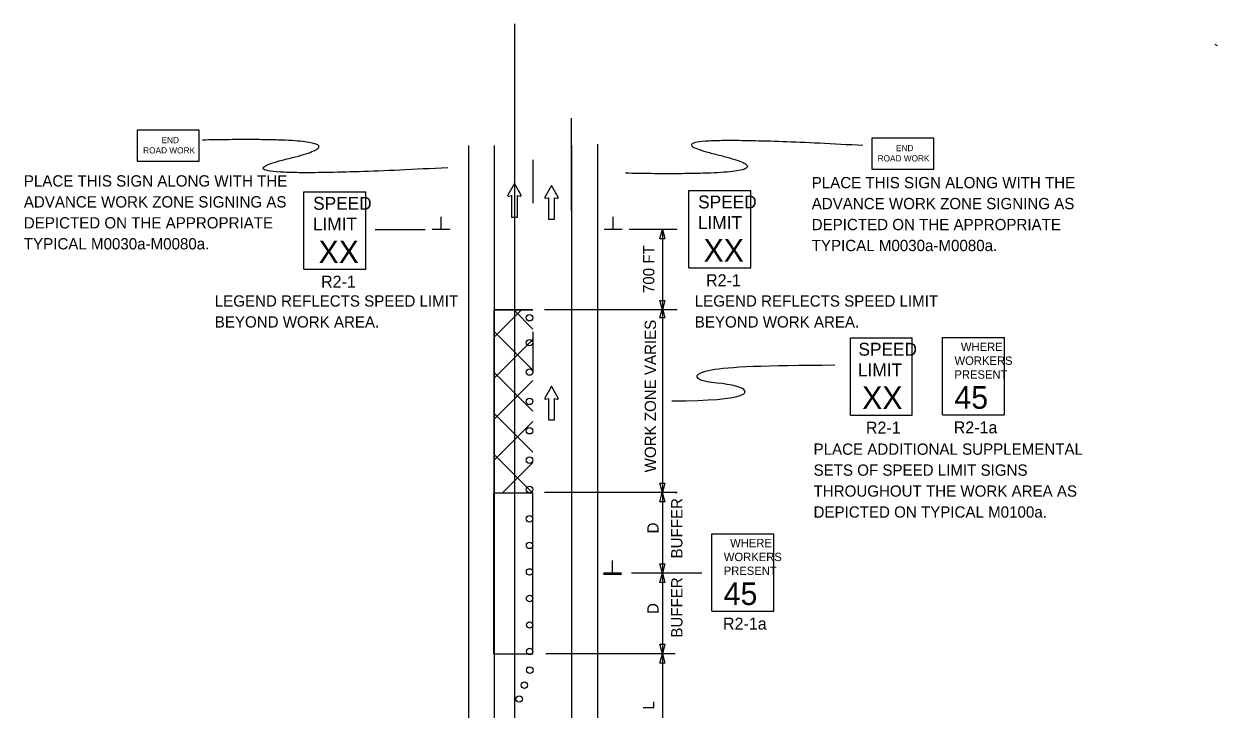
# Model space of a CAD drawing. Extents: x 15278 to 18126, y 1908 to 6555.
# Drawn here: x 15278 to 16017, y 2813 to 3238 of the extents above; entities that cross this region are included whole.
import ezdxf

# ---------------------------------------------------------------- set-up
doc = ezdxf.new("R2010")
doc.units = 0
for name, color, linetype in [('ALI_LEGAL_EX', 7, 'Continuous'), ('MT_SCRATCH_LEVEL_E', 7, 'Continuous'), ('PAVT_EDGE_EX', 7, 'Continuous'), ('TRAFFIC_SIGNS_PR', 7, 'Continuous'), ('TYPICAL_TEXT_DIMEN_PR', 7, 'Continuous')]:
    doc.layers.add(name, color=color, linetype=linetype)

msp = doc.modelspace()

# ---------------------------------------------------------------- linework, layer by layer
at = {"layer": 'ALI_LEGAL_EX'}
msp.add_line((15581.68, 3237.79), (15581.68, 2408.6), dxfattribs=at)
for points in [[(15593.04, 3153.46), (15593.04, 3126.45)], [(15593.04, 3046.7), (15593.04, 3021.3)], [(15593.04, 3021.3), (15593.04, 3021.3)], [(15590.55, 3007.79), (15590.55, 3007.79)]]:
    msp.add_lwpolyline(points, dxfattribs=at)
at = {"layer": 'MT_SCRATCH_LEVEL_E'}
for p, q in [((15581.51, 3138.81), (15577.39, 3131.57)), ((15585.65, 3131.57), (15581.51, 3138.81)), ((15604.48, 3137.54), (15600.37, 3130.3)), ((15608.63, 3130.3), (15604.48, 3137.54)), ((15577.88, 3130.88), (15579.65, 3131.2)), ((15579.65, 3131.2), (15579.65, 3117.94)), ((15583.4, 3117.94), (15583.4, 3131.2)), ((15583.4, 3131.2), (15585.17, 3130.88)), ((15600.85, 3129.61), (15602.63, 3129.93)), ((15602.63, 3129.93), (15602.63, 3116.67)), ((15606.37, 3116.67), (15606.37, 3129.93)), ((15606.37, 3129.93), (15608.15, 3129.61)), ((15579.65, 3117.94), (15583.4, 3117.94)), ((15602.63, 3116.67), (15606.37, 3116.67)), ((15604.48, 3012.92), (15600.37, 3005.68)), ((15608.63, 3005.68), (15604.48, 3012.92)), ((15600.85, 3005), (15602.63, 3005.31)), ((15602.63, 3005.31), (15602.63, 2992.06)), ((15606.37, 2992.06), (15606.37, 3005.31)), ((15606.37, 3005.31), (15608.15, 3005)), ((15602.63, 2992.06), (15606.37, 2992.06))]:
    msp.add_line(p, q, dxfattribs=at)
for centre, start, end in [((15577.8, 3131.34), 150.42484, 279.96381), ((15585.24, 3131.34), 260.03619, 29.77312), ((15600.78, 3130.07), 150.42484, 279.96381), ((15608.22, 3130.07), 260.03619, 29.77312), ((15600.78, 3005.46), 150.42484, 279.96381), ((15608.22, 3005.46), 260.03619, 29.77312)]:
    msp.add_arc(centre, 0.463, start, end, dxfattribs=at)
at = {"layer": 'PAVT_EDGE_EX'}
for p, q in [((15617, 3154.14), (15617, 3179.34)), ((15553, 3162.29), (15553, 2476.81)), ((15569, 3162.29), (15569, 2476.81)), ((15617, 3162.29), (15617, 2476.81)), ((15633, 3163.21), (15633, 2476.81)), ((15617, 3122.08), (15617, 3154.14)), ((15569.04, 2946.61), (15569.04, 3060.33)), ((15569.04, 3060.33), (15593.04, 3060.33)), ((15593.04, 3060.33), (15569.04, 3060.33)), ((15569.04, 3043.52), (15585.85, 3060.33)), ((15593.04, 3048.43), (15581.14, 3060.33)), ((15593.04, 3022.98), (15569.04, 3046.98)), ((15569.04, 3018.07), (15593.04, 3042.07)), ((15593.04, 2997.52), (15569.04, 3021.52)), ((15569.04, 2992.61), (15593.04, 3016.61)), ((15593.04, 2972.07), (15569.04, 2996.07)), ((15569.04, 2967.16), (15593.04, 2991.16)), ((15593.04, 2946.61), (15569.04, 2970.61)), ((15573.95, 2946.61), (15593.04, 2965.7)), ((15592.91, 2946.61), (15569.04, 2946.61)), ((15589.94, 2838.71), (15589.89, 2838.83)), ((15568.93, 2815.26), (15568.88, 2815.38))]:
    msp.add_line(p, q, dxfattribs=at)
msp.add_lwpolyline([(15592.91, 2946.61), (15568.53, 2946.61), (15568.53, 2847.05), (15592.91, 2847.05)], close=True, dxfattribs=at)
at = {"layer": 'TRAFFIC_SIGNS_PR'}
for p, q in [((15451.02, 3133.58), (15489.43, 3133.58)), ((15451.02, 3085.58), (15451.02, 3133.58)), ((15489.43, 3085.58), (15489.43, 3133.58)), ((15689.66, 3134.43), (15728.06, 3134.43)), ((15689.66, 3086.43), (15689.66, 3134.43)), ((15728.06, 3086.43), (15728.06, 3134.43)), ((15451.02, 3085.58), (15489.43, 3085.58)), ((15689.66, 3086.43), (15728.06, 3086.43)), ((15789.78, 3043.07), (15828.18, 3043.07)), ((15789.78, 2995.07), (15789.78, 3043.07)), ((15828.18, 2995.07), (15828.18, 3043.07)), ((15846.98, 3043.15), (15885.38, 3043.15)), ((15846.98, 2995.15), (15846.98, 3043.15)), ((15885.38, 2995.15), (15885.38, 3043.15)), ((15789.78, 2995.07), (15828.18, 2995.07)), ((15846.98, 2995.15), (15885.38, 2995.15)), ((15703.97, 2921.41), (15742.37, 2921.41)), ((15703.97, 2873.41), (15703.97, 2921.41)), ((15742.37, 2873.41), (15742.37, 2921.41)), ((15703.97, 2873.41), (15742.37, 2873.41))]:
    msp.add_line(p, q, dxfattribs=at)
for points in [[(15347.83, 3152.63), (15386.23, 3152.63), (15386.23, 3171.83), (15347.83, 3171.83)], [(15803.06, 3147.67), (15841.46, 3147.67), (15841.46, 3166.87), (15803.06, 3166.87)]]:
    msp.add_lwpolyline(points, close=True, dxfattribs=at)
for centre in [(15590.9, 3055.46), (15590.94, 3040), (15590.94, 3021.78), (15590.94, 3003.57), (15590.94, 2985.36), (15590.94, 2967.14), (15590.94, 2948.93), (15590.94, 2930.71), (15590.96, 2914.25), (15590.97, 2897.79), (15590.99, 2881.32), (15591, 2864.86), (15591.02, 2848.39), (15591.08, 2836.84), (15587.71, 2827.56), (15584.49, 2818.97)]:
    msp.add_circle(centre, 2, dxfattribs=at)
for points in [[(15540.23, 3148.51), (15383.99, 3140.28), (15497.9, 3167.86), (15388.27, 3165.69)], [(15797.61, 3162.28), (15650.05, 3170.51), (15763.95, 3142.93), (15650.5, 3145.1)]]:
    msp.add_open_spline(points, degree=2, dxfattribs=at)
at = {"layer": 'TYPICAL_TEXT_DIMEN_PR'}
for p, q in [((16015.78, 3225.17), (16017.12, 3224.27)), ((15536.12, 3110.35), (15536.12, 3118.14)), ((15642.77, 3110.35), (15642.77, 3118.14)), ((15495.28, 3110.26), (15526.25, 3110.26)), ((15530.5, 3110.35), (15541.75, 3110.35)), ((15637.15, 3110.35), (15648.4, 3110.35)), ((15652.6, 3110.35), (15682.48, 3110.35)), ((15671.68, 3104.49), (15673.25, 3110.35)), ((15671.68, 3104.49), (15673.25, 3110.35)), ((15673.25, 3110.35), (15674.82, 3104.49)), ((15673.25, 3110.35), (15674.82, 3104.49)), ((15673.25, 3110.35), (15673.25, 3060.35)), ((15673.25, 3104.49), (15671.68, 3104.49)), ((15673.25, 3104.49), (15671.68, 3104.49)), ((15674.82, 3104.49), (15673.25, 3104.49)), ((15674.82, 3104.49), (15673.25, 3104.49)), ((15673.25, 3060.35), (15671.68, 3066.21)), ((15671.68, 3066.21), (15673.25, 3066.21)), ((15673.25, 3066.21), (15674.82, 3066.21)), ((15674.82, 3066.21), (15673.25, 3060.35)), ((15682.48, 3060.35), (15600.17, 3060.35)), ((15671.67, 3055.42), (15673.24, 3061.28)), ((15673.24, 3055.42), (15671.67, 3055.42)), ((15673.24, 3061.28), (15674.81, 3055.42)), ((15674.81, 3055.42), (15673.24, 3055.42)), ((15673.25, 3060.35), (15673.25, 2947.05)), ((15673.24, 2946.99), (15671.67, 2952.86)), ((15671.67, 2952.86), (15673.24, 2952.86)), ((15673.24, 2952.86), (15674.81, 2952.86)), ((15674.81, 2952.86), (15673.24, 2946.99)), ((15682.48, 2947.05), (15600.17, 2947.05)), ((15671.65, 2941.19), (15673.22, 2947.05)), ((15673.22, 2947.05), (15674.79, 2941.19)), ((15673.25, 2947.05), (15673.25, 2897.05)), ((15681.18, 2947.05), (15682.48, 2947.05)), ((15673.22, 2941.19), (15671.65, 2941.19)), ((15674.79, 2941.19), (15673.22, 2941.19)), ((15642.37, 2897.04), (15642.37, 2904.82)), ((15642.37, 2896.27), (15642.37, 2904.05)), ((15673.25, 2897.05), (15671.68, 2902.91)), ((15671.68, 2902.91), (15673.25, 2902.91)), ((15673.25, 2902.91), (15674.82, 2902.91)), ((15674.82, 2902.91), (15673.25, 2897.05)), ((15648, 2897.04), (15636.75, 2897.04)), ((15648, 2896.27), (15636.75, 2896.27)), ((15697.72, 2897.05), (15654.18, 2897.05)), ((15671.68, 2891.19), (15673.25, 2897.05)), ((15673.25, 2897.05), (15673.25, 2847.05)), ((15673.25, 2897.05), (15674.82, 2891.19)), ((15673.25, 2891.19), (15671.68, 2891.19)), ((15674.82, 2891.19), (15673.25, 2891.19)), ((15673.25, 2847.05), (15671.68, 2852.91)), ((15671.68, 2852.91), (15673.25, 2852.91)), ((15673.25, 2852.91), (15674.82, 2852.91)), ((15674.82, 2852.91), (15673.25, 2847.05)), ((15681.18, 2847.05), (15601.08, 2847.05)), ((15671.7, 2841.19), (15673.27, 2847.05)), ((15673.27, 2841.19), (15671.7, 2841.19)), ((15673.27, 2847.05), (15673.27, 2778.09)), ((15673.27, 2847.05), (15674.85, 2841.19)), ((15674.85, 2841.19), (15673.27, 2841.19))]:
    msp.add_line(p, q, dxfattribs=at)
msp.add_open_spline([(15679.22, 3003.95), (15727.69, 3003.95), (15727.69, 3014.71), (15692.77, 3014.71), (15692.77, 3024.42), (15736.38, 3025.92), (15780.1, 3026.17)], degree=3, dxfattribs=at)

# ---------------------------------------------------------------- texts
at = {"layer": 'TRAFFIC_SIGNS_PR'}
for s, height, p in [('END', 3.831, (15362.83, 3163.76)), ('ROAD WORK', 3.831, (15351.44, 3157.38)), ('END', 3.831, (15818.06, 3158.8)), ('ROAD WORK', 3.831, (15806.67, 3152.41)), ('PLACE THIS SIGN ALONG WITH THE', 7, (15277.49, 3136.85)), ('PLACE THIS SIGN ALONG WITH THE', 7, (15765.83, 3135.79)), ('ADVANCE WORK ZONE SIGNING AS', 7, (15277.49, 3123.85)), ('SPEED', 8, (15456.79, 3122.44)), ('SPEED', 8, (15695.43, 3123.3)), ('ADVANCE WORK ZONE SIGNING AS', 7, (15765.83, 3122.79)), ('DEPICTED ON THE APPROPRIATE', 7, (15277.49, 3110.85)), ('LIMIT', 8, (15456.63, 3109.64)), ('LIMIT', 8, (15695.27, 3110.5)), ('DEPICTED ON THE APPROPRIATE', 7, (15765.83, 3109.79)), ('TYPICAL M0030a-M0080a.', 7, (15277.49, 3097.85)), ('XX', 14.031, (15460.14, 3089.34)), ('XX', 14.031, (15698.78, 3090.19)), ('TYPICAL M0030a-M0080a.', 7, (15765.83, 3096.79)), ('R2-1', 7.44, (15461.7, 3074.14)), ('R2-1', 7.44, (15700.34, 3074.99)), ('LEGEND REFLECTS SPEED LIMIT', 7, (15395.84, 3062.37)), ('LEGEND REFLECTS SPEED LIMIT', 7, (15693.35, 3062.37)), ('BEYOND WORK AREA.', 7, (15395.84, 3049.37)), ('BEYOND WORK AREA.', 7, (15693.35, 3049.37)), ('SPEED', 8, (15794.81, 3031.93)), ('WHERE', 5.2, (15858.29, 3034.84)), ('LIMIT', 8, (15794.48, 3019.13)), ('WORKERS', 5.2, (15854.36, 3026.24)), ('PRESENT', 5.2, (15854.29, 3017.64)), ('XX', 14.031, (15797.09, 2998.82)), ('45', 14.031, (15854.28, 2999.01)), ('R2-1', 7.44, (15799.39, 2983.63)), ('R2-1a', 7.44, (15853.83, 2983.71)), ('PLACE ADDITIONAL SUPPLEMENTAL', 7, (15766.98, 2970.46)), ('SETS OF SPEED LIMIT SIGNS', 7, (15766.98, 2957.46)), ('THROUGHOUT THE WORK AREA AS', 7, (15766.98, 2944.46)), ('DEPICTED ON TYPICAL M0100a.', 7, (15766.98, 2931.46)), ('WHERE', 5.2, (15715.28, 2913.1)), ('WORKERS', 5.2, (15711.36, 2904.5)), ('PRESENT', 5.2, (15711.29, 2895.9)), ('45', 14.031, (15711.28, 2877.27)), ('R2-1a', 7.44, (15710.83, 2861.97))]:
    msp.add_text(s, height=height, dxfattribs=at).set_placement(p)
at = {"layer": 'TYPICAL_TEXT_DIMEN_PR'}
for s, p in [('700 FT', (15668.29, 3070.77)), ('WORK ZONE VARIES', (15669.31, 2959.57)), ('BUFFER', (15685.71, 2906.16)), ('D', (15670.91, 2921.66)), ('BUFFER', (15685.71, 2857.02)), ('D', (15670.91, 2871.66)), ('L', (15668.29, 2812.44))]:
    msp.add_text(s, height=7, rotation=90, dxfattribs=at).set_placement(p)

doc.saveas('drawing.dxf')
